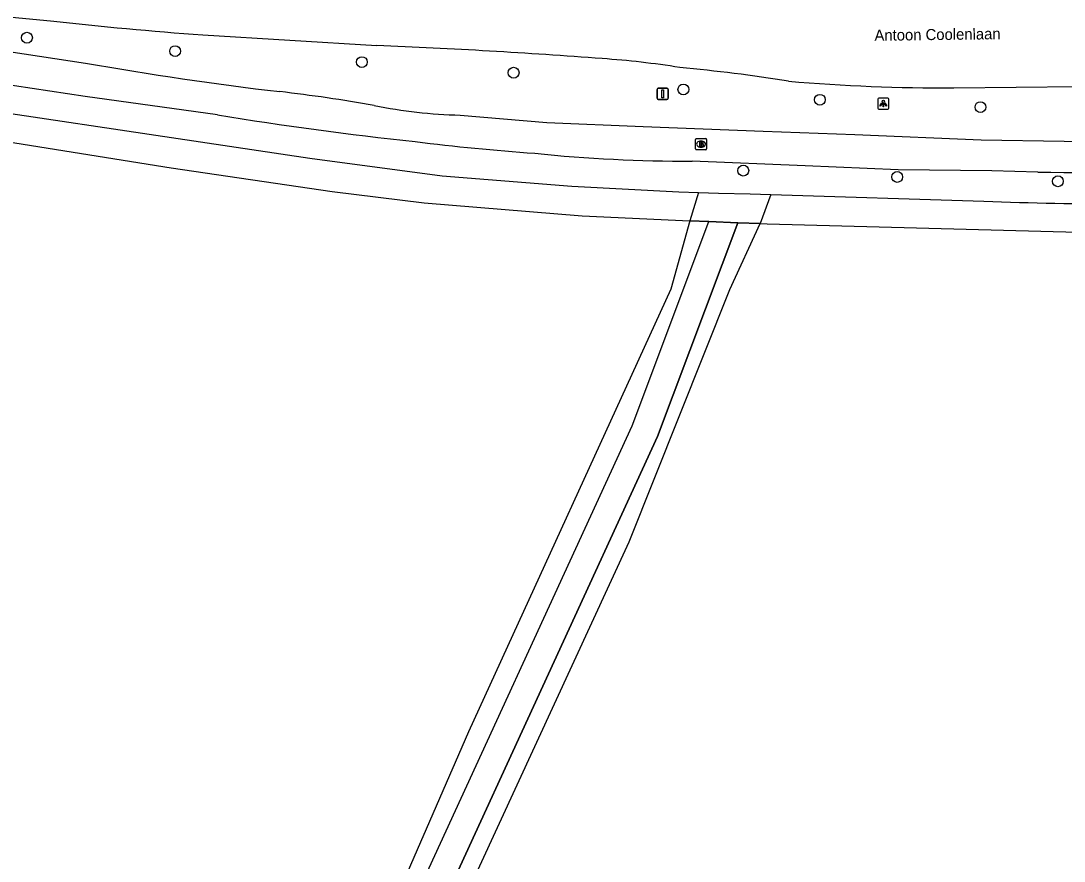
# Model space of a CAD drawing. Extents: x 160203 to 161526, y 379529 to 381797.
# Drawn here: x 160660 to 160754.1, y 380785.1 to 380860.9 of the extents above; entities that cross this region are included whole.
import ezdxf

# ---------------------------------------------------------------- set-up
doc = ezdxf.new("R2010")
doc.units = 0
for name, color, linetype in [('IMGEO_Boom', 7, 'Continuous'), ('IMGEO_Brandkraan', 7, 'Continuous'), ('IMGEO_Fietspad_open', 7, 'Continuous'), ('IMGEO_Grasland_agrarisch', 7, 'Continuous'), ('IMGEO_Groenvoorziening', 7, 'Continuous'), ('IMGEO_Hek', 7, 'Continuous'), ('IMGEO_Houtwal', 7, 'Continuous'), ('IMGEO_Lichtpunt', 7, 'Continuous'), ('IMGEO_Openbare_ruimte_label', 7, 'Continuous'), ('IMGEO_Rijbaan_lokaal_gesloten', 7, 'Continuous'), ('IMGEO_Verkeersbordpaal', 7, 'Continuous'), ('IMGEO_Voetpad_open', 7, 'Continuous')]:
    doc.layers.add(name, color=color, linetype=linetype)

msp = doc.modelspace()

# ---------------------------------------------------------------- linework, layer by layer
at = {"layer": 'IMGEO_Boom'}
for centre in [(160660.529, 380859.363), (160673.9, 380858.149), (160690.748, 380857.161), (160704.435, 380856.202), (160719.749, 380854.689), (160732.065, 380853.763), (160746.551, 380853.099), (160725.153, 380847.365), (160739.042, 380846.799), (160753.538, 380846.409)]:
    msp.add_circle(centre, 0.489, dxfattribs=at)
at = {"layer": 'IMGEO_Brandkraan'}
for p, q in [((160720.843, 380849.333), (160720.843, 380850.185)), ((160720.918, 380850.259), (160721.77, 380850.259)), ((160721.331, 380850.039), (160721.356, 380850.039)), ((160721.844, 380850.185), (160721.844, 380849.333)), ((160721.77, 380849.259), (160720.918, 380849.259)), ((160721.354, 380849.479), (160721.329, 380849.479))]:
    msp.add_line(p, q, dxfattribs=at)
for points in [[(160720.843, 380849.333), (160720.843, 380850.185)], [(160720.918, 380850.259), (160721.77, 380850.259)], [(160721.191, 380849.959), (160721.191, 380849.559), (160721.404, 380849.559)], [(160721.422, 380849.959), (160721.191, 380849.959)], [(160721.37, 380849.878), (160721.316, 380849.878), (160721.316, 380849.802)], [(160721.316, 380849.802), (160721.369, 380849.802)], [(160721.378, 380849.726), (160721.316, 380849.726), (160721.316, 380849.645)], [(160721.316, 380849.645), (160721.378, 380849.645)], [(160721.844, 380850.185), (160721.844, 380849.333)], [(160721.77, 380849.259), (160720.918, 380849.259)]]:
    msp.add_lwpolyline(points, dxfattribs=at)
for centre, radius, start, end in [((160720.92, 380850.183), 0.0765, 91.55205, 178.44795), ((160720.92, 380850.183), 0.0765, 91.55205, 178.44795), ((160721.371, 380849.84), 0.0379, 267.82845, 90.93552), ((160721.379, 380849.685), 0.0404, 269.87594, 90.50774), ((160721.41, 380849.81), 0.251, 268.66757, 293.53466), ((160721.426, 380849.814), 0.145, 59.4692, 91.53667), ((160721.451, 380849.861), 0.0922, 285.51372, 58.15012), ((160721.456, 380849.669), 0.105, 301.31148, 78.98903), ((160721.768, 380850.183), 0.0765, 1.55205, 88.44795), ((160721.768, 380850.183), 0.0765, 1.55205, 88.44795), ((160720.92, 380849.335), 0.0765, 181.55205, 268.44795), ((160720.92, 380849.335), 0.0765, 181.55205, 268.44795), ((160721.768, 380849.335), 0.0765, 271.55205, 358.44795), ((160721.768, 380849.335), 0.0765, 271.55205, 358.44795)]:
    msp.add_arc(centre, radius, start, end, dxfattribs=at)
for centre, major_axis, ratio, start_param, end_param in [((160721.33, 380849.759), (-0.387, 0.002), 0.722429, 4.712389, 7.853982), ((160721.355, 380849.759), (-0.39, 0.002), 0.717154, 1.570796, 4.712389)]:
    msp.add_ellipse(centre, major_axis=major_axis, ratio=ratio, start_param=start_param, end_param=end_param, dxfattribs=at)
at = {"layer": 'IMGEO_Fietspad_open'}
for points in [[(160677.721, 380852.395), (160665.771, 380854.06), (160657.796, 380855.265), (160641.107, 380857.988), (160620.908, 380861.53), (160601.608, 380864.985), (160579.354, 380868.964), (160576.691, 380869.445)], [(160608.164, 380867.139), (160614.976, 380865.727), (160619.826, 380864.848), (160629.695, 380862.988), (160638.885, 380861.265), (160646.411, 380860.024), (160665.816, 380857.079)], [(160699.607, 380852.379), (160707.437, 380851.725), (160716.138, 380851.356), (160726.947, 380850.939), (160735.219, 380850.623), (160746.607, 380850.143), (160754.101, 380850.013)], [(160751.719, 380847.233), (160747.564, 380847.336), (160739.131, 380847.453), (160730.74, 380847.81), (160720.54, 380848.222)]]:
    msp.add_lwpolyline(points, dxfattribs=at)
for centre, radius, start, end in [((160716.891, 381143.025), 290.472, 259.87278, 263.36645), ((160666.53, 380710.2), 145.273, 79.96293, 83.35684), ((160728.003, 381158.133), 309.845, 260.66066, 263.98801), ((160700.702, 380897.116), 44.75, 258.59015, 268.59817), ((160719.95, 381043.695), 195.234, 262.82078, 266.00405), ((160757.511, 380977.397), 127.43, 268.46675, 274.31751), ((160720.106, 380981.05), 132.829, 264.05365, 270.18732), ((160758.146, 381259.181), 411.998, 269.1062, 271.73614)]:
    msp.add_arc(centre, radius, start, end, dxfattribs=at)
at = {"layer": 'IMGEO_Grasland_agrarisch'}
for points in [[(160721.116, 380845.4), (160720.336, 380842.843)], [(160727.643, 380845.203), (160726.668, 380842.596)], [(160720.336, 380842.843), (160718.62, 380836.685), (160700.372, 380796.739), (160686.674, 380765.25), (160666.36, 380730.854), (160621.496, 380699.725)], [(160699.37, 380780.126), (160701.375, 380784.636), (160714.858, 380813.858), (160723.927, 380836.633), (160726.668, 380842.596)]]:
    msp.add_lwpolyline(points, dxfattribs=at)
at = {"layer": 'IMGEO_Groenvoorziening'}
for points in [[(160722.035, 380842.768), (160720.336, 380842.843)], [(160726.668, 380842.596), (160724.662, 380842.651)]]:
    msp.add_lwpolyline(points, dxfattribs=at)
at = {"layer": 'IMGEO_Hek'}
for points in [[(160635.899, 380853.719), (160636.693, 380853.59), (160639.112, 380853.136), (160673.536, 380847.615), (160688.052, 380845.487), (160696.377, 380844.475), (160710.618, 380843.275), (160720.336, 380842.843), (160722.035, 380842.768)], [(160724.662, 380842.651), (160726.668, 380842.596), (160727.305, 380842.579), (160755.37, 380841.813), (160764.499, 380841.725), (160790.967, 380843.218), (160797.794, 380818.979), (160800.72, 380802.882), (160803.667, 380782.861), (160807.097, 380750), (160808.197, 380741.734), (160810.001, 380733.144), (160811.746, 380725.723), (160812.287, 380716.603)], [(160697.759, 380780.526), (160717.426, 380823.366), (160724.662, 380842.651)], [(160722.035, 380842.768), (160724.662, 380842.651)]]:
    msp.add_lwpolyline(points, dxfattribs=at)
at = {"layer": 'IMGEO_Houtwal'}
for points in [[(160669.823, 380728.324), (160676.732, 380740.673), (160681.713, 380751.039), (160694.106, 380778.561), (160715.117, 380824.328), (160722.035, 380842.768)], [(160724.662, 380842.651), (160717.426, 380823.366), (160697.759, 380780.526)], [(160724.662, 380842.651), (160722.035, 380842.768)]]:
    msp.add_lwpolyline(points, dxfattribs=at)
at = {"layer": 'IMGEO_Lichtpunt'}
for p, q in [((160737.294, 380853.816), (160737.294, 380853.009)), ((160737.294, 380853.816), (160737.294, 380853.009)), ((160738.196, 380853.911), (160737.388, 380853.911)), ((160738.196, 380853.911), (160737.388, 380853.911)), ((160738.29, 380853.009), (160738.29, 380853.816)), ((160738.29, 380853.009), (160738.29, 380853.816)), ((160737.388, 380852.915), (160738.196, 380852.915)), ((160737.388, 380852.915), (160738.196, 380852.915))]:
    msp.add_line(p, q, dxfattribs=at)
for points in [[(160737.668, 380853.48), (160737.707, 380853.452), (160737.519, 380853.19), (160737.481, 380853.217), (160737.668, 380853.48)], [(160737.77, 380853.432), (160737.817, 380853.432), (160737.817, 380853.11), (160737.77, 380853.11), (160737.77, 380853.432)], [(160737.88, 380853.452), (160737.918, 380853.479), (160738.105, 380853.217), (160738.066, 380853.189), (160737.88, 380853.452)]]:
    msp.add_lwpolyline(points, dxfattribs=at)
msp.add_circle((160737.793, 380853.614), 0.0994, dxfattribs=at)
for centre, start, end in [((160737.388, 380853.816), 90, 180), ((160737.388, 380853.816), 90, 180), ((160738.196, 380853.816), 0, 90), ((160738.196, 380853.816), 0, 90), ((160737.388, 380853.009), 180, 270), ((160737.388, 380853.009), 180, 270), ((160738.196, 380853.009), 270, 0), ((160738.196, 380853.009), 270, 360)]:
    msp.add_arc(centre, 0.0946, start, end, dxfattribs=at)
at = {"layer": 'IMGEO_Rijbaan_lokaal_gesloten'}
for points in [[(160626.113, 380864.513), (160628.533, 380864.161), (160632.949, 380863.534), (160639.84, 380862.681), (160639.872, 380863.089), (160641.697, 380862.911), (160662.659, 380860.883)], [(160676.391, 380859.621), (160692.094, 380858.655)], [(160744.138, 380854.84), (160755.396, 380854.972), (160759.808, 380854.938), (160764.954, 380855.176)]]:
    msp.add_lwpolyline(points, dxfattribs=at)
for centre, radius, start, end in [((160701.861, 381212.1), 353.398, 263.63121, 265.86708), ((160669.608, 380296.216), 562.888, 85.63683, 87.71052), ((160707.235, 380780.759), 76.889, 80.8812, 86.12544), ((160705.082, 380703.312), 154.034, 80.97515, 84.65853), ((160743.152, 381015.798), 160.961, 265.04302, 270.35087)]:
    msp.add_arc(centre, radius, start, end, dxfattribs=at)
at = {"layer": 'IMGEO_Verkeersbordpaal'}
for p, q in [((160717.383, 380853.897), (160717.383, 380854.697)), ((160717.383, 380854.697), (160717.383, 380853.897)), ((160717.483, 380854.797), (160718.273, 380854.797)), ((160718.273, 380854.797), (160717.483, 380854.797)), ((160718.373, 380854.697), (160718.373, 380853.897)), ((160718.373, 380853.897), (160718.373, 380854.697)), ((160718.273, 380853.797), (160717.483, 380853.797)), ((160717.483, 380853.797), (160718.273, 380853.797))]:
    msp.add_line(p, q, dxfattribs=at)
msp.add_lwpolyline([(160717.803, 380854.672), (160717.953, 380854.672), (160717.953, 380853.922), (160717.803, 380853.922), (160717.803, 380854.672)], dxfattribs=at)
for centre, start, end in [((160717.483, 380854.697), 90, 180), ((160717.483, 380854.697), 90, 180), ((160718.273, 380854.697), 0, 90), ((160718.273, 380854.697), 360, 90), ((160717.483, 380853.897), 180, 270), ((160717.483, 380853.897), 180, 270), ((160718.273, 380853.897), 270, 0), ((160718.273, 380853.897), 270, 0)]:
    msp.add_arc(centre, 0.1, start, end, dxfattribs=at)
at = {"layer": 'IMGEO_Voetpad_open'}
for points in [[(160636.54, 380856.152), (160644.558, 380854.692), (160686.044, 380848.48), (160697.994, 380846.894), (160709.678, 380845.951), (160719.327, 380845.454), (160721.116, 380845.4)], [(160721.116, 380845.4), (160722.916, 380845.346), (160725.787, 380845.259), (160727.643, 380845.203)], [(160727.643, 380845.203), (160746.852, 380844.623)]]:
    msp.add_lwpolyline(points, dxfattribs=at)
msp.add_arc((160757.056, 381074.743), 230.346, 267.46117, 273.85099, dxfattribs=at)

# ---------------------------------------------------------------- texts
at = {"layer": 'IMGEO_Openbare_ruimte_label'}
msp.add_text('Antoon Coolenlaan', height=1, rotation=0.7448, dxfattribs=at).set_placement((160736.998, 380859.08))

doc.saveas('drawing.dxf')
